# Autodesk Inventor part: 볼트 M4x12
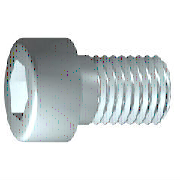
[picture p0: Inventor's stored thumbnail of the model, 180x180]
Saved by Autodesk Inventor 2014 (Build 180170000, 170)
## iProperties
IsCustomPart: 0
Created: 2012-02
Part Number: 볼트 M4x12
Material: 강철, 연강
Description: 6각 소켓 머리 캡 나사
Document SubType Name: Modeling
Standard: ISO 4762
Designer: mduedu
Standard Revision: Fourth edition 2004-03-01
Standards Organization: ISO
Language: ko-KR
Size Designation: M4 x 12
Categories: <MemberInstance><Categories><Category DisplayName="조임쇠" InternalName="e4da775c-781d-43d5-af7c-5136215cf5a6" Mnemonic="FSTN"><Category DisplayName="볼트" InternalN
Density: 7.75 g/cm^3
Appearance: 강철
Author: mduedu
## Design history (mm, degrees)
sketch "스케치1"
  geometry: L1 (-1, 0)-(12, 0); L2 (12, 0)-(12, 2); L3 (12, 2)-(1.75, 2); L4 (1.75, 2)-(1.32, 2); L5 (1.32, 2)-(0, 2); L6 (0, 2)-(0, 3.5); L7 (0, 3.5)-(-4, 3.5); L8 (-4, 3.5)-(-4, 1.732); L9 (-4, 1.732)-(-2, 1.732); L10 (-2, 1.732)-(-1, 0); L11 (-7.2, 0)-(15.2, 0) reference; L12 (0, -0.7)-(0, 4.2) reference; L13 (1.75, 2)-(0, 2)
  constraints: 22 end point, 6 parallel, 2 collinear, 2 perpendicular, 1 horizontal, 1 point on line
  dimensions: "d1" = 10.25 distance from line of L3.end L2 (= GEL); "d2" = 0.42952 distance of L4.end L3.end (computed from GAL); "d3" = 4 distance between parallel lines of L8 L6 (= KOH); "d4" = 2 distance of L8.end L9.end (= INTI); "d5" = 60 deg angle of L10 L1; "d6" = 4 diameter of L3 L1 (= GD); "d7" = 4 diameter of L5 L1 (= BDM); "d8" = 3.4641 diameter of L9 L1 (= 1.1547 x SW); "d9" = 7 diameter of L7 L1 (= KOD); "d26" = 12 distance between parallel lines of L12 L2 (= NLG)
revolve "본체" sketch "스케치1" stored, may be unused: angle "d10" = 90 deg
sketch "스케치2"
  geometry: L1 (0, -4.9)-(0, 4.9) reference; L2 (-4.9, 0)-(4.9, 0) reference; L3 (1.732, 0)-(0.866, -1.5); L4 (0.866, -1.5)-(-0.866, -1.5); L5 (-0.866, -1.5)-(-1.732, 0); L6 (-1.732, 0)-(-0.866, 1.5); L7 (-0.866, 1.5)-(0.866, 1.5); L8 (0.866, 1.5)-(1.732, 0); 2 further points
  constraints: 12 end point, 1 coincident, 1 horizontal alignment, 1 point on line, 12 other
extrude "슬롯" join sketch "스케치2" stored distance "d11" = 10; taper "d12" = 0 deg
workplane "Work Plane1"
fillet "Fillet2" dims "d30" = 0.1 (= R)
body "Solid1"
fillet "모깎기1" dims "d17" = 0.4 (= RR)
feature "스레드" dims "d13" = 10.25 (= GEL), "d14" = 0
chamfer "모따기1" distance "d15" = 0.42941 (= -0.5 x SPD + 0.5 x GD); stored, may be unused: second distance "d16" = 0.42941 (= GUL), angle "d27" = 45 deg
other parameters: "GD" = 4 [user parameter; used in 2 equation terms], "NLG" = 12 [user parameter; used in 1 equation term], "GEL" = 10.25 [user parameter; used in 2 equation terms], "KOD" = 7 [user parameter; used in 1 equation term], "KOH" = 4 [user parameter; used in 1 equation term], "INTI" = 2 [user parameter; used in 1 equation term], "GAL" = 0.42941 (= 0.61345 x PTC) [user parameter; used in 1 equation term], "GUL" = 0.42941 (= 0.61345 x PTC) [user parameter; used in 1 equation term], "BDM" = 4 (= NND) [user parameter; used in 1 equation term], "SW" = 3 [user parameter; used in 2 equation terms], "RR" = 0.4 [user parameter; used in 1 equation term], "SPD" = 3.14117 (= NND - 1.2269 x PTC) [user parameter; used in 1 equation term], "d19" = 0, "d28" = 0, "d29" = 0, "R" = 0.1 [user parameter; used in 1 equation term], "TOA" = 30 deg [user parameter], "GD1" = 3.14117 (= THREADDIA - 1.2269 x PTC) [user parameter], "THREADDIA" = 4 [user parameter; used in 1 equation term], "FAWI" = 45 deg [user parameter], "TPU" = 14.28571 (computed from PTC) [user parameter], "PTC" = 0.7 [user parameter; used in 5 equation terms], "NND" = 4 [user parameter; used in 2 equation terms], "E0" = 3.465 (= 1.155 x SW) [user parameter]
